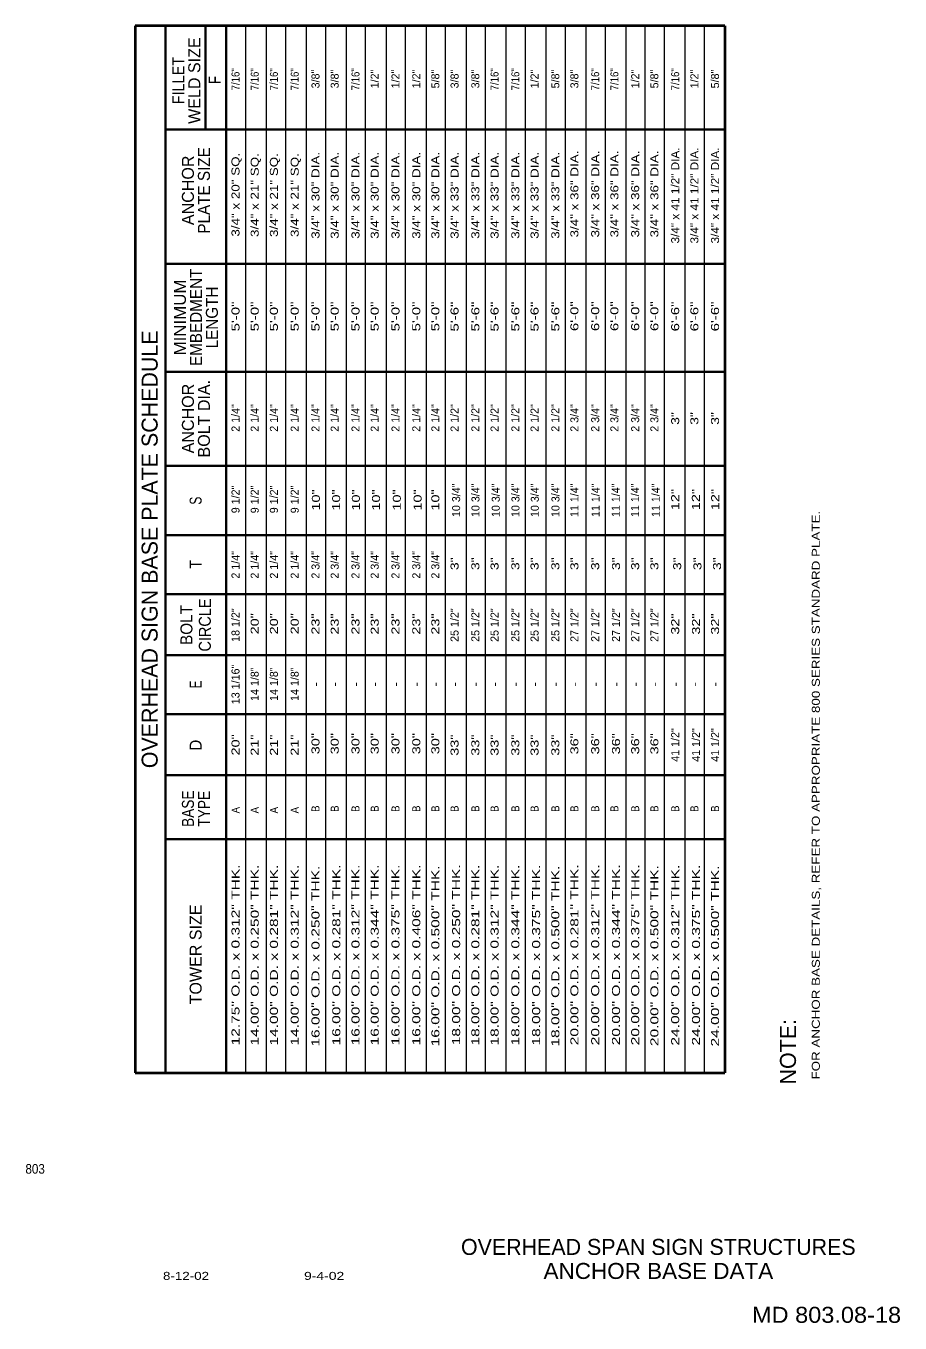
# Model space of a CAD drawing. Extents: x -34866.58 to -34860.02, y -181553.59 to -181543.87.
import ezdxf
from ezdxf.enums import TextEntityAlignment as Align

# ---------------------------------------------------------------- set-up
doc = ezdxf.new("R2010")
doc.units = 0
doc.header["$LTSCALE"] = 0.024
doc.layers.add('1', color=7, linetype='Continuous', lineweight=13)
doc.layers.add('12', color=7, linetype='Continuous')
doc.layers.add('13', color=7, linetype='Continuous')

msp = doc.modelspace()

# ---------------------------------------------------------------- linework, layer by layer
at = {"layer": '1', "lineweight": 40}
for p, q in [((-34865.756, -181543.868), (-34865.756, -181551.716)), ((-34861.332, -181543.868), (-34865.756, -181543.868)), ((-34861.332, -181543.868), (-34861.332, -181551.716)), ((-34865.756, -181551.716), (-34861.332, -181551.716))]:
    msp.add_line(p, q, dxfattribs=at)
at = {"layer": '1', "lineweight": 35}
for p, q in [((-34865.528, -181543.868), (-34865.528, -181551.716)), ((-34865.228, -181543.868), (-34865.228, -181544.645)), ((-34865.073, -181543.868), (-34865.073, -181551.716)), ((-34865.528, -181544.645), (-34861.332, -181544.645)), ((-34865.528, -181545.651), (-34861.332, -181545.651)), ((-34865.528, -181546.462), (-34861.332, -181546.462)), ((-34865.528, -181547.165), (-34861.332, -181547.165)), ((-34865.528, -181547.686), (-34861.332, -181547.686)), ((-34865.528, -181548.129), (-34861.332, -181548.129)), ((-34865.528, -181548.585), (-34861.332, -181548.585)), ((-34865.528, -181549.028), (-34861.332, -181549.028)), ((-34865.528, -181549.484), (-34861.332, -181549.484)), ((-34865.528, -181549.965), (-34861.332, -181549.965))]:
    msp.add_line(p, q, dxfattribs=at)
at = {"layer": '1'}
for p, q in [((-34864.929, -181543.868), (-34864.929, -181551.716)), ((-34864.773, -181543.868), (-34864.773, -181551.716)), ((-34864.629, -181543.868), (-34864.629, -181551.716)), ((-34864.473, -181543.868), (-34864.473, -181551.716)), ((-34864.329, -181543.868), (-34864.329, -181551.716)), ((-34864.173, -181543.868), (-34864.173, -181551.716)), ((-34864.03, -181543.868), (-34864.03, -181551.716)), ((-34863.874, -181543.868), (-34863.874, -181551.716)), ((-34863.73, -181543.868), (-34863.73, -181551.716)), ((-34863.574, -181543.868), (-34863.574, -181551.716)), ((-34863.43, -181543.868), (-34863.43, -181551.716)), ((-34863.274, -181543.868), (-34863.274, -181551.716)), ((-34863.13, -181543.868), (-34863.13, -181551.716)), ((-34862.975, -181543.868), (-34862.975, -181551.716)), ((-34862.831, -181543.868), (-34862.831, -181551.716)), ((-34862.675, -181543.868), (-34862.675, -181551.716)), ((-34862.531, -181543.868), (-34862.531, -181551.716)), ((-34862.375, -181543.868), (-34862.375, -181551.716)), ((-34862.231, -181543.868), (-34862.231, -181551.716)), ((-34862.075, -181543.868), (-34862.075, -181551.716)), ((-34861.932, -181543.868), (-34861.932, -181551.716)), ((-34861.788, -181543.868), (-34861.788, -181551.716)), ((-34861.632, -181543.868), (-34861.632, -181551.716)), ((-34861.488, -181543.868), (-34861.488, -181551.716))]:
    msp.add_line(p, q, dxfattribs=at)

# ---------------------------------------------------------------- texts
at = {"layer": '12'}
for s, height, p in [('WELD SIZE', 0.09, (-34865.267, -181544.278)), ('ANCHOR', 0.09, (-34865.315, -181545.1005)), ('OVERHEAD SIGN BASE PLATE SCHEDULE', 0.12, (-34865.587, -181547.792)), ('ANCHOR', 0.09, (-34865.315, -181546.8115)), ('BOLT DIA.', 0.09, (-34865.195, -181546.8125)), ('TOWER SIZE', 0.09, (-34865.257, -181550.829)), ('NOTE:', 0.12, (-34860.799, -181551.5585))]:
    msp.add_text(s, height=height, rotation=90, dxfattribs=at).set_placement(p, align=Align.CENTER)
for s, width, p in [('FILLET', 0.9, (-34865.387, -181544.2775)), ('F', 0.8, (-34865.114, -181544.2735)), ('PLATE SIZE', 0.95, (-34865.195, -181545.101)), ('EMBEDMENT', 0.95, (-34865.255, -181546.0525)), ('MINIMUM', 1.05, (-34865.375, -181546.0535)), ('LENGTH', 0.95, (-34865.135, -181546.0535)), ('S', 0.75, (-34865.257, -181547.427)), ('T', 0.85, (-34865.257, -181547.9045)), ('BOLT', 0.95, (-34865.326, -181548.3595)), ('CIRCLE', 0.9, (-34865.188, -181548.3595)), ('E', 0.75, (-34865.257, -181548.805)), ('D', 0.95, (-34865.257, -181549.2605)), ('BASE', 0.85, (-34865.315, -181549.7365)), ('TYPE', 0.85, (-34865.195, -181549.7365))]:
    msp.add_text(s, height=0.09, rotation=90, dxfattribs=dict(at, width=width)).set_placement(p, align=Align.CENTER)
at = {"layer": '13'}
for s, width, p in [('7/16"', 0.9, (-34864.973, -181544.268)), ('7/16"', 0.9, (-34864.829, -181544.268)), ('7/16"', 0.9, (-34864.685, -181544.268)), ('7/16"', 0.9, (-34864.529, -181544.268)), ('7/16"', 0.9, (-34864.073, -181544.268)), ('7/16"', 0.9, (-34863.03, -181544.268)), ('7/16"', 0.9, (-34862.874, -181544.268)), ('7/16"', 0.9, (-34862.275, -181544.268)), ('7/16"', 0.9, (-34862.131, -181544.268)), ('7/16"', 0.9, (-34861.675, -181544.268)), ('3/4" x 20" SQ.', 1.25, (-34864.973, -181545.133)), ('3/4" x 21" SQ.', 1.25, (-34864.829, -181545.136)), ('3/4" x 21" SQ.', 1.25, (-34864.685, -181545.136)), ('3/4" x 21" SQ.', 1.25, (-34864.529, -181545.136)), ('3/4" x 30" DIA.', 1.25, (-34864.373, -181545.138)), ('3/4" x 30" DIA.', 1.25, (-34864.229, -181545.138)), ('3/4" x 30" DIA.', 1.25, (-34864.073, -181545.138)), ('3/4" x 30" DIA.', 1.25, (-34863.929, -181545.138)), ('3/4" x 30" DIA.', 1.25, (-34863.773, -181545.138)), ('3/4" x 30" DIA.', 1.25, (-34863.617, -181545.138)), ('3/4" x 30" DIA.', 1.25, (-34863.474, -181545.138)), ('3/4" x 33" DIA.', 1.25, (-34863.33, -181545.138)), ('3/4" x 33" DIA.', 1.25, (-34863.174, -181545.138)), ('3/4" x 33" DIA.', 1.25, (-34863.03, -181545.138)), ('3/4" x 33" DIA.', 1.25, (-34862.874, -181545.138)), ('3/4" x 33" DIA.', 1.25, (-34862.73, -181545.138)), ('3/4" x 33" DIA.', 1.25, (-34862.574, -181545.138)), ('3/4" x 36" DIA.', 1.25, (-34862.431, -181545.128)), ('3/4" x 36" DIA.', 1.25, (-34862.275, -181545.128)), ('3/4" x 36" DIA.', 1.25, (-34862.131, -181545.128)), ('3/4" x 36" DIA.', 1.25, (-34861.975, -181545.128)), ('3/4" x 36" DIA.', 1.25, (-34861.831, -181545.128)), ('3/4" x 41 1/2" DIA.', 1.1, (-34861.675, -181545.139)), ('3/4" x 41 1/2" DIA.', 1.1, (-34861.531, -181545.139)), ('3/4" x 41 1/2" DIA.', 1.1, (-34861.376, -181545.139)), ('5\'-0"', 1.4, (-34864.973, -181546.046)), ('5\'-0"', 1.4, (-34864.829, -181546.046)), ('5\'-0"', 1.4, (-34864.685, -181546.046)), ('5\'-0"', 1.4, (-34864.529, -181546.046)), ('5\'-0"', 1.4, (-34864.373, -181546.046)), ('5\'-0"', 1.4, (-34864.229, -181546.046)), ('5\'-0"', 1.4, (-34864.073, -181546.046)), ('5\'-0"', 1.4, (-34863.929, -181546.046)), ('5\'-0"', 1.4, (-34863.773, -181546.046)), ('5\'-0"', 1.4, (-34863.617, -181546.046)), ('5\'-0"', 1.4, (-34863.474, -181546.046)), ('5\'-6"', 1.4, (-34863.33, -181546.047)), ('5\'-6"', 1.4, (-34863.174, -181546.047)), ('5\'-6"', 1.4, (-34863.03, -181546.047)), ('5\'-6"', 1.4, (-34862.874, -181546.047)), ('5\'-6"', 1.4, (-34862.73, -181546.047)), ('5\'-6"', 1.4, (-34862.574, -181546.047)), ('6\'-0"', 1.4, (-34862.431, -181546.044)), ('6\'-0"', 1.4, (-34862.275, -181546.044)), ('6\'-0"', 1.4, (-34862.131, -181546.044)), ('6\'-0"', 1.4, (-34861.975, -181546.044)), ('6\'-0"', 1.4, (-34861.831, -181546.044)), ('6\'-6"', 1.4, (-34861.675, -181546.046)), ('6\'-6"', 1.4, (-34861.531, -181546.046)), ('6\'-6"', 1.4, (-34861.376, -181546.046)), ('3"', 1.3, (-34861.675, -181546.811)), ('3"', 1.3, (-34861.531, -181546.811)), ('3"', 1.3, (-34861.376, -181546.811)), ('10"', 1.35, (-34864.37, -181547.422)), ('10"', 1.35, (-34864.218, -181547.422)), ('10"', 1.35, (-34864.07, -181547.422)), ('10"', 1.35, (-34863.919, -181547.422)), ('10"', 1.35, (-34863.763, -181547.422)), ('10"', 1.35, (-34863.607, -181547.422)), ('10"', 1.35, (-34863.474, -181547.422)), ('12"', 1.35, (-34861.675, -181547.419)), ('12"', 1.35, (-34861.52, -181547.419)), ('12"', 1.35, (-34861.375, -181547.419)), ('FOR ANCHOR BASE DETAILS, REFER TO APPROPRIATE 800 SERIES STANDARD PLATE.', 1.25, (-34860.62, -181549.635)), ('3"', 1.3, (-34863.33, -181547.9)), ('3"', 1.3, (-34863.174, -181547.9)), ('3"', 1.3, (-34863.03, -181547.9)), ('3"', 1.3, (-34862.874, -181547.9)), ('3"', 1.3, (-34862.73, -181547.9)), ('3"', 1.3, (-34862.574, -181547.9)), ('3"', 1.3, (-34862.431, -181547.9)), ('3"', 1.3, (-34862.275, -181547.9)), ('3"', 1.3, (-34862.119, -181547.9)), ('3"', 1.3, (-34861.975, -181547.9)), ('3"', 1.3, (-34861.831, -181547.9)), ('3"', 1.3, (-34861.66, -181547.9)), ('3"', 1.3, (-34861.508, -181547.9)), ('3"', 1.3, (-34861.361, -181547.9)), ('20"', 1.35, (-34864.829, -181548.35)), ('20"', 1.35, (-34864.685, -181548.35)), ('20"', 1.35, (-34864.529, -181548.35)), ('23"', 1.35, (-34864.373, -181548.352)), ('23"', 1.35, (-34864.229, -181548.352)), ('23"', 1.35, (-34864.073, -181548.352)), ('23"', 1.35, (-34863.929, -181548.352)), ('23"', 1.35, (-34863.773, -181548.352)), ('23"', 1.35, (-34863.617, -181548.352)), ('23"', 1.35, (-34863.474, -181548.352)), ('32"', 1.35, (-34861.675, -181548.352)), ('32"', 1.35, (-34861.519, -181548.352)), ('32"', 1.35, (-34861.376, -181548.352)), ('-', 1.3, (-34864.373, -181548.805)), ('-', 1.3, (-34864.229, -181548.805)), ('-', 1.3, (-34864.073, -181548.805)), ('-', 1.3, (-34863.929, -181548.805)), ('-', 1.3, (-34863.773, -181548.805)), ('-', 1.3, (-34863.617, -181548.805)), ('-', 1.3, (-34863.474, -181548.805)), ('-', 1.3, (-34863.33, -181548.805)), ('-', 1.3, (-34863.174, -181548.805)), ('-', 1.3, (-34863.03, -181548.805)), ('-', 1.3, (-34862.874, -181548.805)), ('-', 1.3, (-34862.73, -181548.805)), ('-', 1.3, (-34862.574, -181548.805)), ('-', 1.3, (-34862.431, -181548.805)), ('-', 1.3, (-34862.275, -181548.805)), ('-', 1.3, (-34862.119, -181548.805)), ('-', 1.3, (-34861.975, -181548.805)), ('-', 1.3, (-34861.831, -181548.805)), ('-', 1.3, (-34861.675, -181548.805)), ('-', 1.3, (-34861.531, -181548.805)), ('-', 1.3, (-34861.376, -181548.805)), ('20"', 1.35, (-34864.973, -181549.258)), ('21"', 1.35, (-34864.829, -181549.26)), ('21"', 1.35, (-34864.685, -181549.26)), ('21"', 1.35, (-34864.529, -181549.26)), ('30"', 1.35, (-34864.373, -181549.249)), ('30"', 1.35, (-34864.229, -181549.249)), ('30"', 1.35, (-34864.073, -181549.249)), ('30"', 1.35, (-34863.929, -181549.249)), ('30"', 1.35, (-34863.773, -181549.249)), ('30"', 1.35, (-34863.617, -181549.249)), ('30"', 1.35, (-34863.474, -181549.249)), ('33"', 1.35, (-34863.33, -181549.26)), ('33"', 1.35, (-34863.174, -181549.26)), ('33"', 1.35, (-34863.03, -181549.26)), ('33"', 1.35, (-34862.874, -181549.26)), ('33"', 1.35, (-34862.73, -181549.26)), ('33"', 1.35, (-34862.574, -181549.26)), ('36"', 1.35, (-34862.431, -181549.25)), ('36"', 1.35, (-34862.275, -181549.25)), ('36"', 1.35, (-34862.119, -181549.25)), ('36"', 1.35, (-34861.975, -181549.25)), ('36"', 1.35, (-34861.831, -181549.25)), ('A', 0.9, (-34864.973, -181549.7475)), ('A', 0.9, (-34864.829, -181549.7475)), ('A', 0.9, (-34864.685, -181549.7475)), ('A', 0.9, (-34864.529, -181549.7475)), ('B', 0.9, (-34864.373, -181549.7365)), ('B', 0.9, (-34864.229, -181549.7365)), ('B', 0.9, (-34864.073, -181549.7365)), ('B', 0.9, (-34863.929, -181549.7365)), ('B', 0.9, (-34863.773, -181549.7365)), ('B', 0.9, (-34863.617, -181549.7365)), ('B', 0.9, (-34863.474, -181549.7365)), ('B', 0.9, (-34863.33, -181549.7365)), ('B', 0.9, (-34863.174, -181549.7365)), ('B', 0.9, (-34863.03, -181549.7365)), ('B', 0.9, (-34862.874, -181549.7365)), ('B', 0.9, (-34862.73, -181549.7365)), ('B', 0.9, (-34862.574, -181549.7365)), ('B', 0.9, (-34862.431, -181549.7365)), ('B', 0.9, (-34862.275, -181549.7365)), ('B', 0.9, (-34862.131, -181549.7365)), ('B', 0.9, (-34861.975, -181549.7365)), ('B', 0.9, (-34861.831, -181549.7365)), ('B', 0.9, (-34861.675, -181549.7365)), ('B', 0.9, (-34861.531, -181549.7365)), ('B', 0.9, (-34861.376, -181549.7365)), ('12.75" O.D. x 0.312" THK.', 1.45, (-34864.973, -181550.833)), ('14.00" O.D. x 0.250" THK.', 1.45, (-34864.829, -181550.834)), ('14.00" O.D. x 0.281" THK.', 1.45, (-34864.685, -181550.834)), ('14.00" O.D. x 0.312" THK.', 1.45, (-34864.529, -181550.834)), ('16.00" O.D. x 0.250" THK.', 1.45, (-34864.373, -181550.842)), ('16.00" O.D. x 0.281" THK.', 1.45, (-34864.217, -181550.833)), ('16.00" O.D. x 0.312" THK.', 1.45, (-34864.073, -181550.833)), ('16.00" O.D. x 0.344" THK.', 1.45, (-34863.929, -181550.833)), ('16.00" O.D. x 0.375" THK.', 1.45, (-34863.773, -181550.833)), ('16.00" O.D. x 0.406" THK.', 1.45, (-34863.617, -181550.833)), ('16.00" O.D. x 0.500" THK.', 1.45, (-34863.474, -181550.84)), ('18.00" O.D. x 0.250" THK.', 1.45, (-34863.318, -181550.832)), ('18.00" O.D. x 0.281" THK.', 1.45, (-34863.174, -181550.834)), ('18.00" O.D. x 0.312" THK.', 1.45, (-34863.03, -181550.834)), ('18.00" O.D. x 0.344" THK.', 1.45, (-34862.874, -181550.834)), ('18.00" O.D. x 0.375" THK.', 1.45, (-34862.718, -181550.834)), ('18.00" O.D. x 0.500" THK.', 1.45, (-34862.574, -181550.842)), ('20.00" O.D. x 0.281" THK.', 1.45, (-34862.431, -181550.832)), ('20.00" O.D. x 0.312" THK.', 1.45, (-34862.275, -181550.832)), ('20.00" O.D. x 0.344" THK.', 1.45, (-34862.119, -181550.832)), ('20.00" O.D. x 0.375" THK.', 1.45, (-34861.975, -181550.832)), ('20.00" O.D. x 0.500" THK.', 1.45, (-34861.831, -181550.838)), ('24.00" O.D. x 0.312" THK.', 1.45, (-34861.675, -181550.834)), ('24.00" O.D. x 0.375" THK.', 1.45, (-34861.519, -181550.834)), ('24.00" O.D. x 0.500" THK.', 1.45, (-34861.376, -181550.841))]:
    msp.add_text(s, height=0.06, rotation=90, dxfattribs=dict(at, width=width)).set_placement(p, align=Align.CENTER)
for s, p in [('3/8"', (-34864.373, -181544.266)), ('3/8"', (-34864.229, -181544.266)), ('1/2"', (-34863.929, -181544.266)), ('1/2"', (-34863.773, -181544.266)), ('1/2"', (-34863.617, -181544.266)), ('5/8"', (-34863.474, -181544.266)), ('3/8"', (-34863.33, -181544.266)), ('3/8"', (-34863.174, -181544.266)), ('1/2"', (-34862.73, -181544.266)), ('5/8"', (-34862.574, -181544.266)), ('3/8"', (-34862.431, -181544.266)), ('1/2"', (-34861.975, -181544.266)), ('5/8"', (-34861.831, -181544.266)), ('1/2"', (-34861.531, -181544.266)), ('5/8"', (-34861.376, -181544.266)), ('2 1/4"', (-34864.973, -181546.807)), ('2 1/4"', (-34864.829, -181546.807)), ('2 1/4"', (-34864.685, -181546.807)), ('2 1/4"', (-34864.529, -181546.807)), ('2 1/4"', (-34864.373, -181546.807)), ('2 1/4"', (-34864.229, -181546.807)), ('2 1/4"', (-34864.073, -181546.807)), ('2 1/4"', (-34863.929, -181546.807)), ('2 1/4"', (-34863.773, -181546.807)), ('2 1/4"', (-34863.617, -181546.807)), ('2 1/4"', (-34863.474, -181546.807)), ('2 1/2"', (-34863.33, -181546.807)), ('2 1/2"', (-34863.174, -181546.807)), ('2 1/2"', (-34863.03, -181546.807)), ('2 1/2"', (-34862.874, -181546.807)), ('2 1/2"', (-34862.73, -181546.807)), ('2 1/2"', (-34862.574, -181546.807)), ('2 3/4"', (-34862.431, -181546.807)), ('2 3/4"', (-34862.275, -181546.807)), ('2 3/4"', (-34862.131, -181546.807)), ('2 3/4"', (-34861.975, -181546.807)), ('2 3/4"', (-34861.831, -181546.807)), ('9 1/2"', (-34864.973, -181547.418)), ('9 1/2"', (-34864.829, -181547.418)), ('9 1/2"', (-34864.685, -181547.418)), ('9 1/2"', (-34864.529, -181547.418)), ('10 3/4"', (-34863.318, -181547.424)), ('10 3/4"', (-34863.173, -181547.424)), ('10 3/4"', (-34863.021, -181547.424)), ('10 3/4"', (-34862.873, -181547.424)), ('10 3/4"', (-34862.728, -181547.424)), ('10 3/4"', (-34862.573, -181547.424)), ('11 1/4"', (-34862.431, -181547.424)), ('11 1/4"', (-34862.272, -181547.424)), ('11 1/4"', (-34862.121, -181547.424)), ('11 1/4"', (-34861.976, -181547.424)), ('11 1/4"', (-34861.821, -181547.424)), ('2 1/4"', (-34864.973, -181547.908)), ('2 1/4"', (-34864.829, -181547.908)), ('2 1/4"', (-34864.685, -181547.908)), ('2 1/4"', (-34864.529, -181547.908)), ('2 3/4"', (-34864.373, -181547.908)), ('2 3/4"', (-34864.229, -181547.908)), ('2 3/4"', (-34864.073, -181547.908)), ('2 3/4"', (-34863.929, -181547.908)), ('2 3/4"', (-34863.773, -181547.908)), ('2 3/4"', (-34863.617, -181547.908)), ('2 3/4"', (-34863.474, -181547.908)), ('18 1/2"', (-34864.973, -181548.36)), ('25 1/2"', (-34863.33, -181548.36)), ('25 1/2"', (-34863.174, -181548.36)), ('25 1/2"', (-34863.03, -181548.36)), ('25 1/2"', (-34862.874, -181548.36)), ('25 1/2"', (-34862.73, -181548.36)), ('25 1/2"', (-34862.574, -181548.36)), ('27 1/2"', (-34862.431, -181548.36)), ('27 1/2"', (-34862.275, -181548.36)), ('27 1/2"', (-34862.119, -181548.36)), ('27 1/2"', (-34861.975, -181548.36)), ('27 1/2"', (-34861.831, -181548.36)), ('13 1/16"', (-34864.973, -181548.805)), ('14 1/8"', (-34864.829, -181548.803)), ('14 1/8"', (-34864.685, -181548.803)), ('14 1/8"', (-34864.529, -181548.803)), ('41 1/2"', (-34861.675, -181549.259)), ('41 1/2"', (-34861.519, -181549.259)), ('41 1/2"', (-34861.376, -181549.259))]:
    msp.add_text(s, height=0.06, rotation=90, dxfattribs=at).set_placement(p, align=Align.CENTER)
for s, height, width, p in [('803', 0.07251, 0.9, (-34866.506, -181552.473)), ('ANCHOR BASE DATA', 0.12, 1.05, (-34861.831, -181553.262))]:
    msp.add_text(s, height=height, dxfattribs=dict(at, width=width)).set_placement(p, align=Align.CENTER)
msp.add_text('OVERHEAD SPAN SIGN STRUCTURES', height=0.12, dxfattribs=at).set_placement((-34861.8315, -181553.082), align=Align.CENTER)
for s, height, width, p in [('8-12-02', 0.06, 1.25, (-34865.547, -181553.269)), ('9-4-02', 0.06, 1.3, (-34864.489, -181553.269)), ('MD 803.08-18', 0.12, 1.1, (-34861.129, -181553.591))]:
    msp.add_text(s, height=height, dxfattribs=dict(at, width=width)).set_placement(p)

doc.saveas('drawing.dxf')
